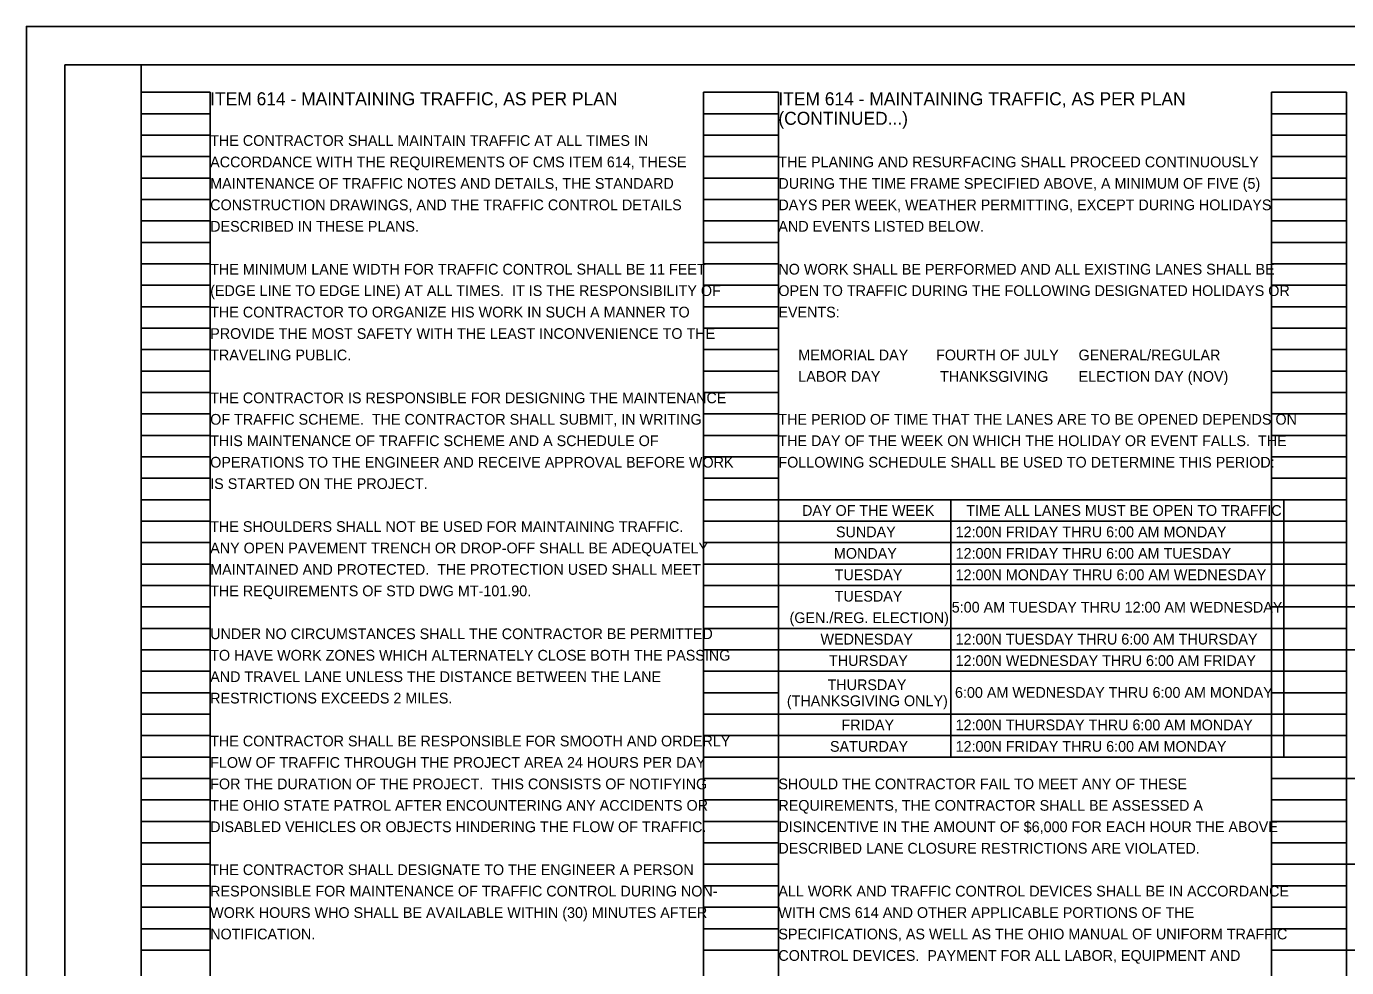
# Model space of a CAD drawing. Extents: x 0 to 34, y 0 to 22.
# Drawn here: x 0 to 17.24, y 9.71 to 22 of the extents above; entities that cross this region are included whole.
import ezdxf

# ---------------------------------------------------------------- set-up
doc = ezdxf.new("R2010")
doc.units = 0
for name, color, linetype in [('SH_Border', 7, 'Continuous'), ('SH_Cut_Line', 7, 'Continuous'), ('SH_Data', 7, 'Continuous'), ('SH_Text', 7, 'Continuous')]:
    doc.layers.add(name, color=color, linetype=linetype)

msp = doc.modelspace()

# ---------------------------------------------------------------- linework, layer by layer
at = {"layer": 'SH_Border'}
for points in [[(0.5, 21.5), (1.5, 21.5), (1.5, 0.5), (0.5, 0.5)], [(1.5, 21.5), (33.5, 21.5), (33.5, 0.5), (1.5, 0.5)]]:
    msp.add_lwpolyline(points, close=True, dxfattribs=at)
at = {"layer": 'SH_Cut_Line'}
msp.add_lwpolyline([(0, 0), (34, 0), (34, 22), (0, 22)], close=True, dxfattribs=at)
at = {"layer": 'SH_Data'}
for p, q in [((1.5, 0.98), (1.5, 21.14)), ((1.5, 21.14), (2.4, 21.14)), ((2.4, 0.98), (2.4, 21.14)), ((8.84, 0.98), (8.84, 21.14)), ((8.84, 21.14), (9.82, 21.14)), ((9.82, 0.98), (9.82, 21.14)), ((16.26, 0.98), (16.26, 21.14)), ((16.26, 21.14), (17.24, 21.14)), ((17.24, 0.98), (17.24, 21.14)), ((1.5, 20.86), (2.4, 20.86)), ((8.84, 20.86), (9.82, 20.86)), ((16.26, 20.86), (17.24, 20.86)), ((1.5, 20.58), (2.4, 20.58)), ((8.84, 20.58), (9.82, 20.58)), ((16.26, 20.58), (17.24, 20.58)), ((1.5, 20.3), (2.4, 20.3)), ((8.84, 20.3), (9.82, 20.3)), ((16.26, 20.3), (17.24, 20.3)), ((1.5, 20.02), (2.4, 20.02)), ((8.84, 20.02), (9.82, 20.02)), ((16.26, 20.02), (17.24, 20.02)), ((1.5, 19.74), (2.4, 19.74)), ((8.84, 19.74), (9.82, 19.74)), ((16.26, 19.74), (17.24, 19.74)), ((1.5, 19.46), (2.4, 19.46)), ((8.84, 19.46), (9.82, 19.46)), ((16.26, 19.46), (17.24, 19.46)), ((1.5, 19.18), (2.4, 19.18)), ((8.84, 19.18), (9.82, 19.18)), ((16.26, 19.18), (17.24, 19.18)), ((1.5, 18.9), (2.4, 18.9)), ((8.84, 18.9), (9.82, 18.9)), ((16.26, 18.9), (17.24, 18.9)), ((1.5, 18.62), (2.4, 18.62)), ((8.84, 18.62), (9.82, 18.62)), ((16.26, 18.62), (17.24, 18.62)), ((1.5, 18.34), (2.4, 18.34)), ((8.84, 18.34), (9.82, 18.34)), ((16.26, 18.34), (17.24, 18.34)), ((1.5, 18.06), (2.4, 18.06)), ((8.84, 18.06), (9.82, 18.06)), ((16.26, 18.06), (17.24, 18.06)), ((1.5, 17.78), (2.4, 17.78)), ((8.84, 17.78), (9.82, 17.78)), ((16.26, 17.78), (17.24, 17.78)), ((1.5, 17.5), (2.4, 17.5)), ((8.84, 17.5), (9.82, 17.5)), ((16.26, 17.5), (17.24, 17.5)), ((1.5, 17.22), (2.4, 17.22)), ((8.84, 17.22), (9.82, 17.22)), ((16.26, 17.22), (17.24, 17.22)), ((1.5, 16.94), (2.4, 16.94)), ((8.84, 16.94), (9.82, 16.94)), ((16.26, 16.94), (17.24, 16.94)), ((1.5, 16.66), (2.4, 16.66)), ((8.84, 16.66), (9.82, 16.66)), ((16.26, 16.66), (17.24, 16.66)), ((1.5, 16.38), (2.4, 16.38)), ((8.84, 16.38), (9.82, 16.38)), ((16.26, 16.38), (17.24, 16.38)), ((1.5, 16.1), (2.4, 16.1)), ((8.84, 16.1), (9.82, 16.1)), ((16.26, 16.1), (17.24, 16.1)), ((1.5, 15.82), (2.4, 15.82)), ((8.84, 15.82), (9.82, 15.82)), ((16.26, 15.82), (17.24, 15.82)), ((1.5, 15.54), (2.4, 15.54)), ((8.84, 15.54), (9.82, 15.54)), ((16.26, 15.54), (17.24, 15.54)), ((1.5, 15.26), (2.4, 15.26)), ((8.84, 15.26), (9.82, 15.26)), ((9.82, 15.26), (16.42, 15.26)), ((16.26, 15.26), (17.24, 15.26)), ((1.5, 14.98), (2.4, 14.98)), ((8.84, 14.98), (9.82, 14.98)), ((9.82, 14.98), (16.42, 14.98)), ((16.26, 14.98), (17.24, 14.98)), ((1.5, 14.7), (2.4, 14.7)), ((8.84, 14.7), (9.82, 14.7)), ((9.82, 14.7), (16.42, 14.7)), ((16.26, 14.7), (17.24, 14.7)), ((1.5, 14.42), (2.4, 14.42)), ((8.84, 14.42), (9.82, 14.42)), ((16.26, 14.42), (17.24, 14.42)), ((1.5, 14.14), (2.4, 14.14)), ((8.84, 14.14), (9.82, 14.14)), ((9.82, 14.14), (16.42, 14.14)), ((16.26, 14.14), (17.24, 14.14)), ((1.5, 13.86), (2.4, 13.86)), ((8.84, 13.86), (9.82, 13.86)), ((9.82, 13.86), (16.42, 13.86)), ((16.26, 13.86), (17.24, 13.86)), ((1.5, 13.58), (2.4, 13.58)), ((8.84, 13.58), (9.82, 13.58)), ((9.82, 13.58), (16.42, 13.58)), ((16.26, 13.58), (17.24, 13.58)), ((1.5, 13.3), (2.4, 13.3)), ((8.84, 13.3), (9.82, 13.3)), ((16.26, 13.3), (17.24, 13.3)), ((1.5, 13.02), (2.4, 13.02)), ((8.84, 13.02), (9.82, 13.02)), ((9.82, 13.02), (16.42, 13.02)), ((16.26, 13.02), (17.24, 13.02)), ((1.5, 12.74), (2.4, 12.74)), ((8.84, 12.74), (9.82, 12.74)), ((9.82, 12.74), (16.42, 12.74)), ((16.26, 12.74), (17.24, 12.74)), ((1.5, 12.46), (2.4, 12.46)), ((8.84, 12.46), (9.82, 12.46)), ((9.82, 12.46), (16.42, 12.46)), ((16.26, 12.46), (17.24, 12.46)), ((1.5, 12.18), (2.4, 12.18)), ((8.84, 12.18), (9.82, 12.18)), ((16.26, 12.18), (17.24, 12.18)), ((1.5, 11.9), (2.4, 11.9)), ((8.84, 11.9), (9.82, 11.9)), ((16.26, 11.9), (17.24, 11.9)), ((1.5, 11.62), (2.4, 11.62)), ((8.84, 11.62), (9.82, 11.62)), ((16.26, 11.62), (17.24, 11.62)), ((1.5, 11.34), (2.4, 11.34)), ((8.84, 11.34), (9.82, 11.34)), ((16.26, 11.34), (17.24, 11.34)), ((1.5, 11.06), (2.4, 11.06)), ((8.84, 11.06), (9.82, 11.06)), ((16.26, 11.06), (17.24, 11.06)), ((1.5, 10.78), (2.4, 10.78)), ((8.84, 10.78), (9.82, 10.78)), ((16.26, 10.78), (17.24, 10.78)), ((1.5, 10.5), (2.4, 10.5)), ((8.84, 10.5), (9.82, 10.5)), ((16.26, 10.5), (17.24, 10.5)), ((1.5, 10.22), (2.4, 10.22)), ((8.84, 10.22), (9.82, 10.22)), ((16.26, 10.22), (17.24, 10.22)), ((1.5, 9.94), (2.4, 9.94)), ((8.84, 9.94), (9.82, 9.94)), ((16.26, 9.94), (17.24, 9.94))]:
    msp.add_line(p, q, dxfattribs=at)
at = {"layer": 'SH_Text'}
for p, q in [((9.82, 15.82), (16.42, 15.82)), ((9.82, 15.82), (9.82, 12.46)), ((12.07, 15.82), (12.07, 12.46)), ((16.42, 15.82), (16.42, 12.46)), ((9.82, 15.54), (16.42, 15.54)), ((17.24, 14.42), (23.68, 14.42)), ((17.24, 13.86), (23.68, 13.86)), ((9.82, 12.46), (16.42, 12.46)), ((17.24, 12.18), (23.68, 12.18)), ((17.24, 11.06), (23.68, 11.06))]:
    msp.add_line(p, q, dxfattribs=at)
msp.add_lwpolyline([(17.24, 14.7), (23.68, 14.7), (23.68, 9.94), (17.24, 9.94)], close=True, dxfattribs=at)

# ---------------------------------------------------------------- texts
for s, height, p in [('ITEM 614 - MAINTAINING TRAFFIC, AS PER PLAN', 0.17, (2.4, 20.97)), ('ITEM 614 - MAINTAINING TRAFFIC, AS PER PLAN ', 0.17, (9.82, 20.97)), ('(CONTINUED...)', 0.17, (9.82, 20.715)), ('THE CONTRACTOR SHALL MAINTAIN TRAFFIC AT ALL TIMES IN ', 0.14, (2.4, 20.44)), ('ACCORDANCE WITH THE REQUIREMENTS OF CMS ITEM 614, THESE ', 0.14, (2.4, 20.16)), ('THE PLANING AND RESURFACING SHALL PROCEED CONTINUOUSLY ', 0.14, (9.82, 20.16)), ('MAINTENANCE OF TRAFFIC NOTES AND DETAILS, THE STANDARD ', 0.14, (2.4, 19.88)), ('DURING THE TIME FRAME SPECIFIED ABOVE, A MINIMUM OF FIVE (5) ', 0.14, (9.82, 19.88)), ('CONSTRUCTION DRAWINGS, AND THE TRAFFIC CONTROL DETAILS ', 0.14, (2.4, 19.6)), ('DAYS PER WEEK, WEATHER PERMITTING, EXCEPT DURING HOLIDAYS ', 0.14, (9.82, 19.6)), ('DESCRIBED IN THESE PLANS.', 0.14, (2.4, 19.32)), ('AND EVENTS LISTED BELOW.', 0.14, (9.82, 19.32)), ('THE MINIMUM LANE WIDTH FOR TRAFFIC CONTROL SHALL BE 11 FEET ', 0.14, (2.4, 18.76)), ('NO WORK SHALL BE PERFORMED AND ALL EXISTING LANES SHALL BE ', 0.14, (9.82, 18.76)), ('(EDGE LINE TO EDGE LINE) AT ALL TIMES.  IT IS THE RESPONSIBILITY OF ', 0.14, (2.4, 18.48)), ('OPEN TO TRAFFIC DURING THE FOLLOWING DESIGNATED HOLIDAYS OR ', 0.14, (9.82, 18.48)), ('THE CONTRACTOR TO ORGANIZE HIS WORK IN SUCH A MANNER TO ', 0.14, (2.4, 18.2)), ('EVENTS:', 0.14, (9.82, 18.2)), ('PROVIDE THE MOST SAFETY WITH THE LEAST INCONVENIENCE TO THE ', 0.14, (2.4, 17.92)), ('TRAVELING PUBLIC.', 0.14, (2.4, 17.64)), ('     MEMORIAL DAY       FOURTH OF JULY', 0.14, (9.82, 17.64)), ('GENERAL/REGULAR ', 0.14, (13.74, 17.64)), ('     LABOR DAY               THANKSGIVING', 0.14, (9.82, 17.36)), ('ELECTION DAY (NOV)', 0.14, (13.74, 17.36)), ('THE CONTRACTOR IS RESPONSIBLE FOR DESIGNING THE MAINTENANCE ', 0.14, (2.4, 17.08)), ('OF TRAFFIC SCHEME.  THE CONTRACTOR SHALL SUBMIT, IN WRITING, ', 0.14, (2.4, 16.8)), ('THE PERIOD OF TIME THAT THE LANES ARE TO BE OPENED DEPENDS ON ', 0.14, (9.82, 16.8)), ('THIS MAINTENANCE OF TRAFFIC SCHEME AND A SCHEDULE OF ', 0.14, (2.4, 16.52)), ('THE DAY OF THE WEEK ON WHICH THE HOLIDAY OR EVENT FALLS.  THE ', 0.14, (9.82, 16.52)), ('OPERATIONS TO THE ENGINEER AND RECEIVE APPROVAL BEFORE WORK ', 0.14, (2.4, 16.24)), ('FOLLOWING SCHEDULE SHALL BE USED TO DETERMINE THIS PERIOD:', 0.14, (9.82, 16.24)), ('IS STARTED ON THE PROJECT.', 0.14, (2.4, 15.96)), ('DAY OF THE WEEK', 0.14, (10.129, 15.61)), ('TIME ALL LANES MUST BE OPEN TO TRAFFIC', 0.14, (12.273, 15.61)), ('THE SHOULDERS SHALL NOT BE USED FOR MAINTAINING TRAFFIC.', 0.14, (2.4, 15.4)), ('SUNDAY', 0.14, (10.572, 15.33)), ('12:00N FRIDAY THRU 6:00 AM MONDAY', 0.14, (12.134, 15.33)), ('ANY OPEN PAVEMENT TRENCH OR DROP-OFF SHALL BE ADEQUATELY ', 0.14, (2.4, 15.12)), ('MONDAY', 0.14, (10.545, 15.05)), ('12:00N FRIDAY THRU 6:00 AM TUESDAY', 0.14, (12.134, 15.05)), ('MAINTAINED AND PROTECTED.  THE PROTECTION USED SHALL MEET ', 0.14, (2.4, 14.84)), ('TUESDAY', 0.14, (10.555, 14.77)), ('12:00N MONDAY THRU 6:00 AM WEDNESDAY', 0.14, (12.134, 14.77)), ('THE REQUIREMENTS OF STD DWG MT-101.90.', 0.14, (2.4, 14.56)), ('TUESDAY', 0.14, (10.555, 14.49)), ('5:00 AM TUESDAY THRU 12:00 AM WEDNESDAY', 0.14, (12.084, 14.347)), ('(GEN./REG. ELECTION)', 0.14, (9.966, 14.21)), ('UNDER NO CIRCUMSTANCES SHALL THE CONTRACTOR BE PERMITTED ', 0.14, (2.4, 14)), ('WEDNESDAY', 0.14, (10.37, 13.93)), ('12:00N TUESDAY THRU 6:00 AM THURSDAY', 0.14, (12.134, 13.93)), ('TO HAVE WORK ZONES WHICH ALTERNATELY CLOSE BOTH THE PASSING ', 0.14, (2.4, 13.72)), ('THURSDAY', 0.14, (10.481, 13.65)), ('12:00N WEDNESDAY THRU 6:00 AM FRIDAY', 0.14, (12.134, 13.65)), ('AND TRAVEL LANE UNLESS THE DISTANCE BETWEEN THE LANE ', 0.14, (2.4, 13.44)), ('THURSDAY', 0.14, (10.462, 13.335)), ('RESTRICTIONS EXCEEDS 2 MILES.', 0.14, (2.4, 13.16)), ('6:00 AM WEDNESDAY THRU 6:00 AM MONDAY', 0.14, (12.126, 13.234)), ('(THANKSGIVING ONLY)', 0.14, (9.931, 13.125)), ('FRIDAY', 0.14, (10.644, 12.81)), ('12:00N THURSDAY THRU 6:00 AM MONDAY', 0.14, (12.134, 12.81)), ('THE CONTRACTOR SHALL BE RESPONSIBLE FOR SMOOTH AND ORDERLY ', 0.14, (2.4, 12.6)), ('SATURDAY', 0.14, (10.494, 12.53)), ('12:00N FRIDAY THRU 6:00 AM MONDAY', 0.14, (12.134, 12.53)), ('FLOW OF TRAFFIC THROUGH THE PROJECT AREA 24 HOURS PER DAY ', 0.14, (2.4, 12.32)), ('FOR THE DURATION OF THE PROJECT.  THIS CONSISTS OF NOTIFYING ', 0.14, (2.4, 12.04)), ('SHOULD THE CONTRACTOR FAIL TO MEET ANY OF THESE ', 0.14, (9.82, 12.04)), ('THE OHIO STATE PATROL AFTER ENCOUNTERING ANY ACCIDENTS OR ', 0.14, (2.4, 11.76)), ('REQUIREMENTS, THE CONTRACTOR SHALL BE ASSESSED A ', 0.14, (9.82, 11.76)), ('DISABLED VEHICLES OR OBJECTS HINDERING THE FLOW OF TRAFFIC.', 0.14, (2.4, 11.48)), ('DISINCENTIVE IN THE AMOUNT OF $6,000 FOR EACH HOUR THE ABOVE ', 0.14, (9.82, 11.48)), ('DESCRIBED LANE CLOSURE RESTRICTIONS ARE VIOLATED. ', 0.14, (9.82, 11.2)), ('THE CONTRACTOR SHALL DESIGNATE TO THE ENGINEER A PERSON ', 0.14, (2.4, 10.92)), ('RESPONSIBLE FOR MAINTENANCE OF TRAFFIC CONTROL DURING NON-', 0.14, (2.4, 10.64)), ('ALL WORK AND TRAFFIC CONTROL DEVICES SHALL BE IN ACCORDANCE', 0.14, (9.82, 10.64)), ('WORK HOURS WHO SHALL BE AVAILABLE WITHIN (30) MINUTES AFTER ', 0.14, (2.4, 10.36)), ('WITH CMS 614 AND OTHER APPLICABLE PORTIONS OF THE ', 0.14, (9.82, 10.36)), ('NOTIFICATION.', 0.14, (2.4, 10.08)), ('SPECIFICATIONS, AS WELL AS THE OHIO MANUAL OF UNIFORM TRAFFIC', 0.14, (9.82, 10.08)), ('CONTROL DEVICES.  PAYMENT FOR ALL LABOR, EQUIPMENT AND ', 0.14, (9.82, 9.8))]:
    msp.add_text(s, height=height, dxfattribs=at).set_placement(p)

doc.saveas('drawing.dxf')
